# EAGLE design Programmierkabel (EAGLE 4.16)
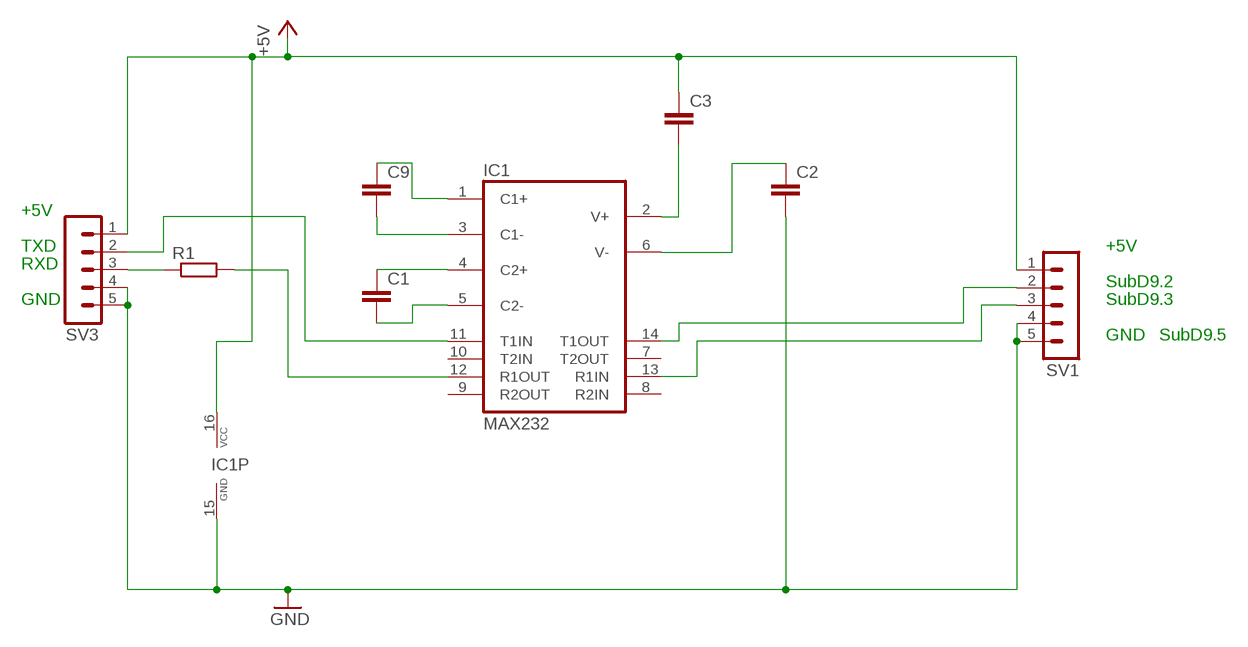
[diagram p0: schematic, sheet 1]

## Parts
C1  C-EU050-025X075  [C050-025X075]
C2  C-EU050-025X075  [C050-025X075]
C3  C-EU050-025X075  [C050-025X075]
C9  C-EU050-025X075  [C050-025X075]
IC1  MAX232  [DIL16]
R1  R-EU_0207/12  [0207/12]
SV1  MA05-1  [MA05-1]
SV3  MA05-1  [MA05-1]

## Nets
+5V: C3.2 IC1.16(VCC) SV1.1 SV3.1
GND: C2.1 IC1.15(GND) SV1.4 SV1.5 SV3.4 SV3.5
N$1: IC1.14(T1OUT) SV1.2
N$2: IC1.13(R1IN) SV1.3
N$6: R1.1 SV3.3
N$7: IC1.12(R1OUT) R1.2
N$8: IC1.11(T1IN) SV3.2
N$9: C9.2 IC1.1(C1+)
N$10: C9.1 IC1.3(C1-)
N$11: C1.2 IC1.4(C2+)
N$12: C1.1 IC1.5(C2-)
N$13: C3.1 IC1.2(V+)
N$14: C2.2 IC1.6(V-)
Unconnected: IC1.7(T2OUT) IC1.8(R2IN) IC1.9(R2OUT) IC1.10(T2IN)

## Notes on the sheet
- +5V
- TXD | +5V
- RXD
- SubD9.2
- GND | SubD9.3
- GND | SubD9.5

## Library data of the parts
C1-C3 C9 = rcl:C-EU: CAPACITOR, European symbol
IC1 = maxim:MAX232: RS232 TRANSEIVER
R1 = rcl:R-EU_: RESISTOR, European symbol
SV1 SV3 = con-lstb:MA05-1: PIN HEADER

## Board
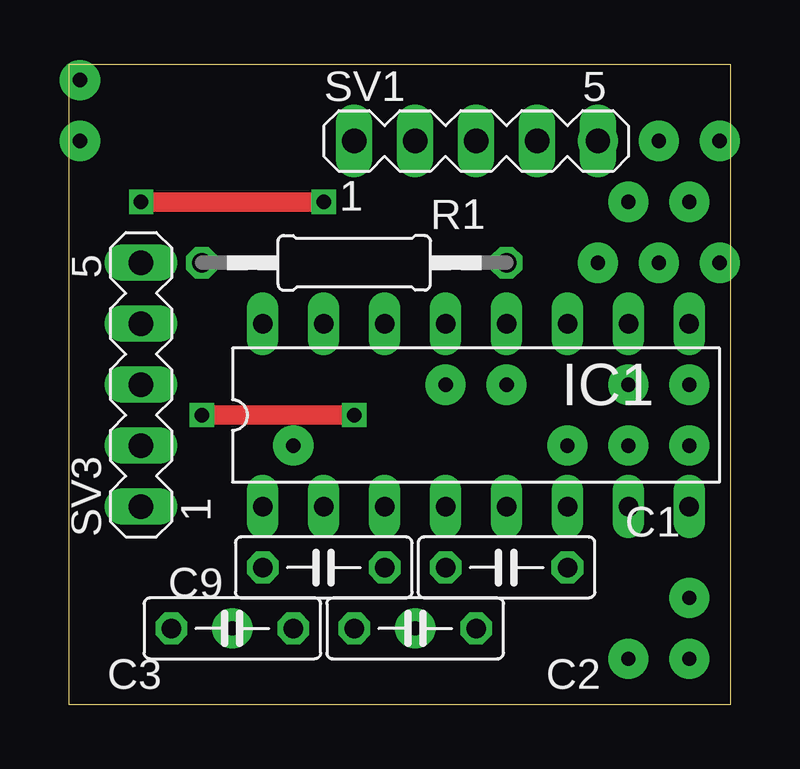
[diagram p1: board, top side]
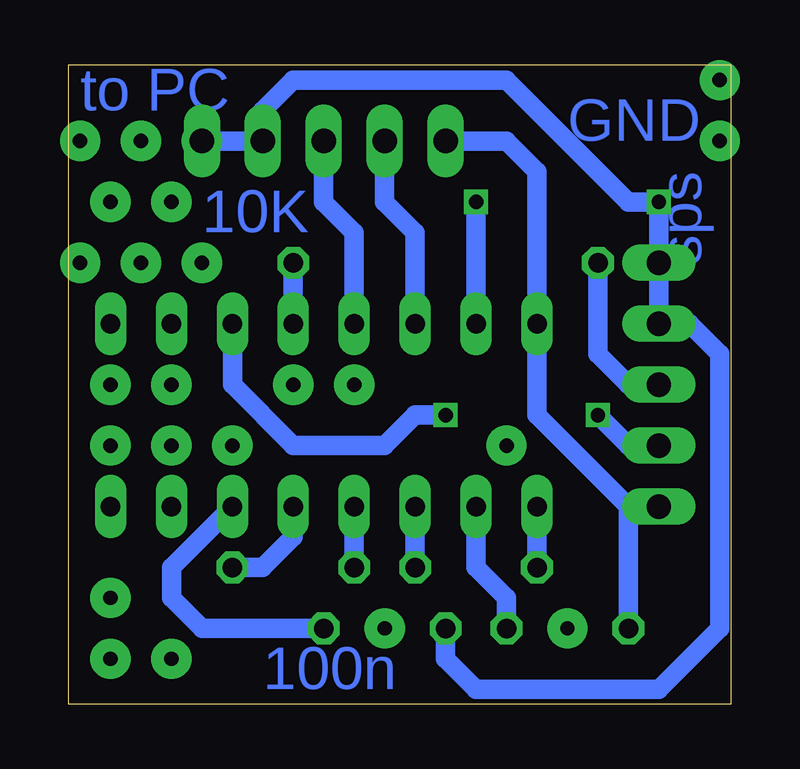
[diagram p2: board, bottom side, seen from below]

Size 27.61 x 26.66 mm. Coordinates in mm from the lower left corner, seen from the top.
Outline: 0,0 27.61,0 27.61,26.66 0,26.66 0,0
Copper layers (1*16): Top 0.035mm / dielectric 1.5mm / Bottom 0.035mm
Design rules "default": minimum track width 10mil, minimum drill 24mil, track to track 8mil, track to pad 8mil, pad to pad 8mil, via to via 8mil, smd to smd 8mil, copper to edge 40mil, drill to drill 8mil, minimum pad ring 10mil, minimum via ring 8mil, stop-mask expansion 4mil, vias tented up to drill 0mil, thermal gap 10mil

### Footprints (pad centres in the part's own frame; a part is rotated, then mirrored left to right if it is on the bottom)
C050-025X075 = drill 0.813 octagon: 1 -2.54,0; 2 2.54,0
DIL16 = drill 0.813 long: 1 -8.89,-3.81; 2 -6.35,-3.81; 3 -3.81,-3.81; 4 -1.27,-3.81; 5 1.27,-3.81; 6 3.81,-3.81; 7 6.35,-3.81; 8 8.89,-3.81; 9 8.89,3.81; 10 6.35,3.81; 11 3.81,3.81; 12 1.27,3.81; 13 -1.27,3.81; 14 -3.81,3.81; 15 -6.35,3.81; 16 -8.89,3.81
0207/12 = drill 0.813 octagon: 1 -6.35,0; 2 6.35,0
MA05-1 = drill 1.016 long: 1 -5.08,0; 2 -2.54,0; 3 0,0; 4 2.54,0; 5 5.08,0

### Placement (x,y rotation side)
C1  18.25,5.71 180 top
C2  14.44,3.17 0 top
C3  6.82,3.17 180 top
C9  10.63,5.71 180 top
IC1  16.98,12.06 0 top
R1  11.9,18.41 0 top
SV1  16.98,23.49 0 top
SV3  3.01,13.33 90 top

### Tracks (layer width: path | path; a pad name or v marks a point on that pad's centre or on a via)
+5V
  Bottom 0.813: IC1.16 8.09,17.14 | 4.28,8.25 8.09,12.06 IC1.16 | IC1.16 8.09,22.22 9.36,23.49 SV1.1 | 4.28,8.25 SV3.1 | C3.2 4.28,8.25
GND  (via drill 0.6)
  Top 0.813: v3.01,20.95 v10.63,20.95
  Bottom 0.813: C2.1 11.9,1.9 10.63,0.63 3.01,0.63 0.47,3.17 0.47,14.6 1.74,15.87 SV3.4 SV3.5 | v10.63,20.95 IC1.15 | v3.01,20.95 4.28,20.95 9.36,26.03 18.25,26.03 19.52,24.76 SV1.4 SV1.5 | SV3.5 v3.01,20.95 | SV3.5 v3.01,20.95
N$1
  Bottom 0.813: IC1.14 13.17,19.68 14.44,20.95 SV1.2
N$2
  Bottom 0.813: IC1.13 15.71,19.68 16.98,20.95 SV1.3
N$3  (via drill 0.6 pad 1.68)
  other vias: 22.06,23.49
N$4  (via drill 0.6 pad 1.68)
  other vias: 24.6,23.49
N$5  (via drill 0.6 pad 1.68)
  other vias: 27.14,23.49
N$6
  Bottom 0.813: R1.1 5.55,14.6 4.28,13.33 SV3.3
N$7
  Bottom 0.813: IC1.12 R1.2
N$8  (via drill 0.6)
  Top 0.813: v5.55,12.06 v11.9,12.06
  Bottom 0.813: IC1.11 20.79,13.33 18.25,10.79 14.44,10.79 13.17,12.06 v11.9,12.06 | v5.55,12.06 4.28,10.79 SV3.2
N$9
  Bottom 0.813: C9.2 IC1.1
N$10
  Bottom 0.813: C9.1 IC1.3
N$11
  Bottom 0.813: C1.2 IC1.4
N$12
  Bottom 0.813: C1.1 19.52,5.71 18.25,6.98 IC1.5
N$13
  Bottom 0.813: C3.1 9.36,4.44 10.63,5.71 IC1.2
N$14
  Bottom 0.813: IC1.6 23.33,5.71 23.33,4.44 22.06,3.17 C2.2
N$15  (via drill 0.6 pad 1.68)
  other vias: 23.33,20.95
N$16  (via drill 0.6 pad 1.68)
  other vias: 25.87,20.95
N$17  (via drill 0.6 pad 1.68)
  other vias: 22.06,18.41
N$18  (via drill 0.6 pad 1.68)
  other vias: 24.6,18.41
N$19  (via drill 0.6 pad 1.68)
  other vias: 27.14,18.41
N$20  (via drill 0.6 pad 1.68)
  other vias: 23.33,13.33
N$21  (via drill 0.6 pad 1.68)
  other vias: 25.87,13.33
N$22  (via drill 0.6 pad 1.68)
  other vias: 20.79,10.79
N$23  (via drill 0.6 pad 1.68)
  other vias: 23.33,10.79
N$24  (via drill 0.6 pad 1.68)
  other vias: 25.87,10.79
N$25  (via drill 0.6 pad 1.68)
  other vias: 18.25,13.33
N$26  (via drill 0.6 pad 1.68)
  other vias: 15.71,13.33
N$27  (via drill 0.6 pad 1.68)
  other vias: 9.36,10.79
N$28  (via drill 0.6 pad 1.68)
  other vias: 6.82,3.17
N$29  (via drill 0.6 pad 1.68)
  other vias: 14.44,3.17
N$30  (via drill 0.6 pad 1.68)
  other vias: 23.33,1.9
N$31  (via drill 0.6 pad 1.68)
  other vias: 25.87,1.9
N$32  (via drill 0.6 pad 1.68)
  other vias: 25.87,4.44
N$33  (via drill 0.6 pad 1.68)
  other vias: 0.47,26.03
N$34  (via drill 0.6 pad 1.68)
  other vias: 0.47,23.49

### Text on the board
Bottom: to PC | GND | sps | 10K | 100n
